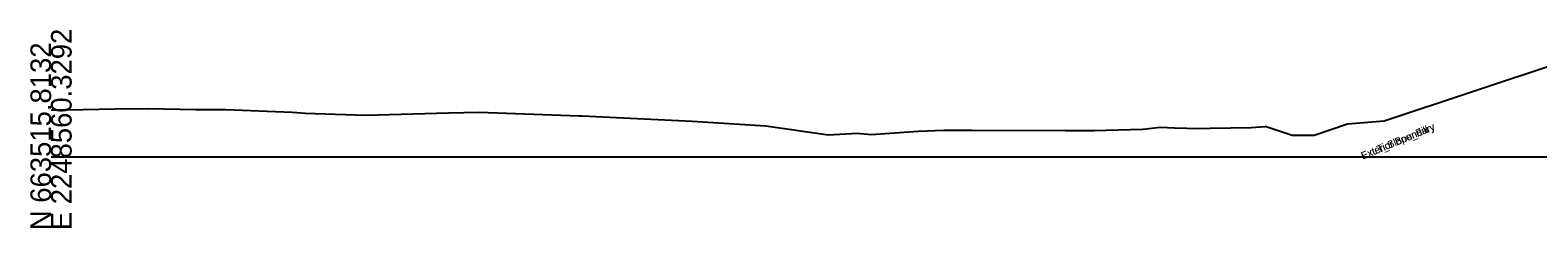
# Model space of a CAD drawing. Extents: x -26 to 2603, y -10 to 9566.
# Drawn here: x 997.2 to 1202.3, y 990.3 to 1017.3 of the extents above; entities that cross this region are included whole.
import ezdxf

# ---------------------------------------------------------------- set-up
doc = ezdxf.new("R2010")
doc.units = 0
for name, color, linetype in [('Default', 7, 'Continuous'), ('Exist Cross Section Cell', 7, 'Continuous'), ('Exist XS Ground Line', 7, 'Continuous'), ('Scratch_Level_9', 7, 'Continuous')]:
    doc.layers.add(name, color=color, linetype=linetype)

msp = doc.modelspace()

# ---------------------------------------------------------------- linework, layer by layer
at = {"layer": 'Exist Cross Section Cell'}
msp.add_line((1000, 1000), (1300, 1000), dxfattribs=at)
at = {"layer": 'Exist XS Ground Line'}
for p, q in [((1000, 1006.39), (1008.73, 1006.54)), ((1008.73, 1006.54), (1013.28, 1006.62)), ((1013.28, 1006.62), (1019.68, 1006.46)), ((1019.68, 1006.46), (1022.92, 1006.46)), ((1022.92, 1006.46), (1023.77, 1006.47)), ((1023.77, 1006.47), (1032.8, 1006.09)), ((1032.8, 1006.09), (1033.46, 1006.06)), ((1033.46, 1006.06), (1034.6, 1005.96)), ((1034.6, 1005.96), (1042.81, 1005.67)), ((1042.81, 1005.67), (1054.07, 1006.01)), ((1054.07, 1006.01), (1058.24, 1006.12)), ((1058.24, 1006.12), (1071.87, 1005.6)), ((1071.87, 1005.6), (1072.29, 1005.58)), ((1072.29, 1005.58), (1087.22, 1004.88)), ((1087.22, 1004.88), (1097.25, 1004.22)), ((1097.25, 1004.22), (1105.79, 1003.01)), ((1105.79, 1003.01), (1109.71, 1003.25)), ((1109.71, 1003.25), (1111.62, 1003.07)), ((1111.62, 1003.07), (1117.98, 1003.49)), ((1117.98, 1003.49), (1121.5, 1003.64)), ((1121.5, 1003.64), (1125.35, 1003.64)), ((1125.35, 1003.64), (1138.02, 1003.6)), ((1138.02, 1003.6), (1140.52, 1003.58)), ((1140.52, 1003.58), (1141.26, 1003.6)), ((1141.26, 1003.6), (1141.91, 1003.6)), ((1141.91, 1003.6), (1148.56, 1003.79)), ((1148.56, 1003.79), (1150.95, 1004.06)), ((1150.95, 1004.06), (1152.89, 1003.96)), ((1152.89, 1003.96), (1156.24, 1003.85)), ((1156.24, 1003.85), (1157.73, 1003.9)), ((1157.73, 1003.9), (1163.32, 1004.01)), ((1163.32, 1004.01), (1165.21, 1004.15))]:
    msp.add_line(p, q, dxfattribs=at)
for points in [[(1205.58, 1012.91), (1181.41, 1004.86)], [(1181.41, 1004.86), (1176.41, 1004.44), (1171.87, 1002.93), (1168.87, 1002.93), (1165.21, 1004.15)]]:
    msp.add_lwpolyline(points, dxfattribs=at)

# ---------------------------------------------------------------- texts
at = {"layer": 'Default'}
msp.add_text('-', height=0.0001, dxfattribs=at).set_placement((1000, 1000))
msp.add_text('-', height=0.0001, dxfattribs=at).set_placement((1000, 1000))
msp.add_text('-', height=0.0001, dxfattribs=at).set_placement((1000, 1000))
msp.add_text('-', height=0.0001, dxfattribs=at).set_placement((1000, 1000))
msp.add_text('-', height=0.0001, dxfattribs=at).set_placement((1000, 1000))
at = {"layer": 'Exist Cross Section Cell'}
for s, p in [('E 2248560.3292', (1002.8, 990)), ('N 663515.8132', (1000, 990))]:
    msp.add_text(s, height=2.8, rotation=90, dxfattribs=at).set_placement(p)
at = {"layer": 'Scratch_Level_9'}
for s, p in [('Exterior Boundary', (1178.5, 999.63)), ('Exterior Boundary', (1178.54, 999.63)), ('LT_Slope_Fill', (1179.96, 1000.23))]:
    msp.add_text(s, height=1, rotation=22.5575, dxfattribs=at).set_placement(p)

doc.saveas('drawing.dxf')
